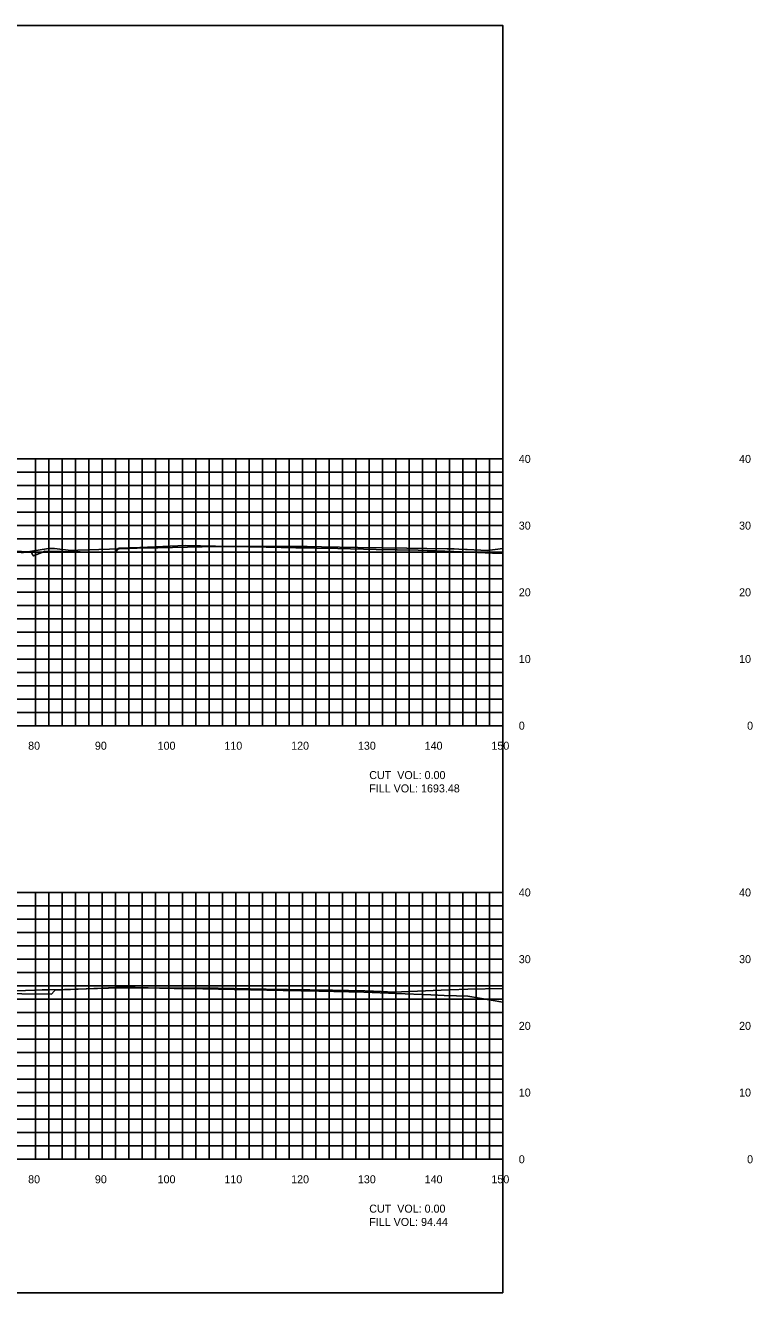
# Model space of a CAD drawing. Extents: x 1797518 to 1804843, y 248068 to 251132.
# Drawn here: x 1802709.5 to 1802818.4, y 250079.4 to 250269.4 of the extents above; entities that cross this region are included whole.
import ezdxf

# ---------------------------------------------------------------- set-up
doc = ezdxf.new("R2010")
doc.units = 0
for name, color, linetype in [('10', 7, 'Continuous'), ('31', 7, 'Continuous'), ('60', 7, 'Continuous'), ('ANNO-TXT', 7, 'Continuous'), ('CL-CNST', 7, 'Continuous'), ('Level 62', 7, 'Continuous'), ('M-ROADS', 7, 'Continuous')]:
    doc.layers.add(name, color=color, linetype=linetype)

msp = doc.modelspace()

# ---------------------------------------------------------------- linework, layer by layer
msp.add_lwpolyline([(1802481, 250079.43), (1802781, 250079.43), (1802781, 250269.43), (1802481, 250269.43)], close=True)
at = {"layer": '60'}
for p, q in [((1802781, 250164.43), (1802781, 250204.43)), ((1802781.06, 250204.43), (1802781, 250204.43)), ((1802781.06, 250194.43), (1802781, 250194.43)), ((1802781.06, 250184.43), (1802781, 250184.43)), ((1802781.06, 250174.43), (1802781, 250174.43)), ((1802481, 250164.43), (1802781, 250164.43)), ((1802711, 250164.37), (1802711, 250164.43)), ((1802721, 250164.37), (1802721, 250164.43)), ((1802731, 250164.37), (1802731, 250164.43)), ((1802741, 250164.37), (1802741, 250164.43)), ((1802751, 250164.37), (1802751, 250164.43)), ((1802761, 250164.37), (1802761, 250164.43)), ((1802771, 250164.37), (1802771, 250164.43)), ((1802781, 250164.37), (1802781, 250164.43)), ((1802781.06, 250164.43), (1802781, 250164.43)), ((1802781, 250099.43), (1802781, 250139.43)), ((1802781.06, 250139.43), (1802781, 250139.43)), ((1802781.06, 250129.43), (1802781, 250129.43)), ((1802781.06, 250119.43), (1802781, 250119.43)), ((1802781.06, 250109.43), (1802781, 250109.43)), ((1802481, 250099.43), (1802781, 250099.43)), ((1802711, 250099.37), (1802711, 250099.43)), ((1802721, 250099.37), (1802721, 250099.43)), ((1802731, 250099.37), (1802731, 250099.43)), ((1802741, 250099.37), (1802741, 250099.43)), ((1802751, 250099.37), (1802751, 250099.43)), ((1802761, 250099.37), (1802761, 250099.43)), ((1802771, 250099.37), (1802771, 250099.43)), ((1802781, 250099.37), (1802781, 250099.43)), ((1802781.06, 250099.43), (1802781, 250099.43))]:
    msp.add_line(p, q, dxfattribs=at)
at = {"layer": 'CL-CNST'}
for points in [[(1802707.78, 250190.58), (1802710.13, 250190.49), (1802710.29, 250190.48), (1802710.35, 250190.48), (1802710.59, 250190.02), (1802710.68, 250189.88), (1802711.96, 250190.4), (1802712.4, 250190.58), (1802715.12, 250190.53), (1802722.9, 250190.42), (1802723.07, 250190.61), (1802723.45, 250191.03), (1802726.65, 250191.17), (1802733.49, 250191.45), (1802737.96, 250191.36), (1802745.55, 250191.2), (1802750.02, 250191.11), (1802756.27, 250190.98), (1802762.05, 250190.86), (1802768.31, 250190.74), (1802773.66, 250190.53), (1802778.34, 250190.35), (1802779.46, 250190.31), (1802780.35, 250190.28), (1802781, 250190.25)], [(1802704.47, 250124.27), (1802713.39, 250124.19), (1802713.78, 250124.63), (1802713.94, 250124.8), (1802720.89, 250125.09), (1802723.99, 250125.21), (1802731.8, 250125.05), (1802736.05, 250124.96), (1802740.75, 250124.87), (1802748.11, 250124.72), (1802753.45, 250124.61), (1802760.18, 250124.47), (1802765.1, 250124.28), (1802770.23, 250124.08), (1802771.27, 250124.04), (1802772.24, 250124), (1802774.09, 250123.93), (1802775.76, 250123.87), (1802781, 250123)]]:
    msp.add_lwpolyline(points, dxfattribs=at)
at = {"layer": 'Level 62'}
for p, q in [((1802481, 250204.43), (1802781, 250204.43)), ((1802711, 250164.43), (1802711, 250204.43)), ((1802713, 250164.43), (1802713, 250204.43)), ((1802715, 250164.43), (1802715, 250204.43)), ((1802717, 250164.43), (1802717, 250204.43)), ((1802719, 250164.43), (1802719, 250204.43)), ((1802721, 250164.43), (1802721, 250204.43)), ((1802723, 250164.43), (1802723, 250204.43)), ((1802725, 250164.43), (1802725, 250204.43)), ((1802727, 250164.43), (1802727, 250204.43)), ((1802729, 250164.43), (1802729, 250204.43)), ((1802731, 250164.43), (1802731, 250204.43)), ((1802733, 250164.43), (1802733, 250204.43)), ((1802735, 250164.43), (1802735, 250204.43)), ((1802737, 250164.43), (1802737, 250204.43)), ((1802739, 250164.43), (1802739, 250204.43)), ((1802741, 250164.43), (1802741, 250204.43)), ((1802743, 250164.43), (1802743, 250204.43)), ((1802745, 250164.43), (1802745, 250204.43)), ((1802747, 250164.43), (1802747, 250204.43)), ((1802749, 250164.43), (1802749, 250204.43)), ((1802751, 250164.43), (1802751, 250204.43)), ((1802753, 250164.43), (1802753, 250204.43)), ((1802755, 250164.43), (1802755, 250204.43)), ((1802757, 250164.43), (1802757, 250204.43)), ((1802759, 250164.43), (1802759, 250204.43)), ((1802761, 250164.43), (1802761, 250204.43)), ((1802763, 250164.43), (1802763, 250204.43)), ((1802765, 250164.43), (1802765, 250204.43)), ((1802767, 250164.43), (1802767, 250204.43)), ((1802769, 250164.43), (1802769, 250204.43)), ((1802771, 250164.43), (1802771, 250204.43)), ((1802773, 250164.43), (1802773, 250204.43)), ((1802775, 250164.43), (1802775, 250204.43)), ((1802777, 250164.43), (1802777, 250204.43)), ((1802779, 250164.43), (1802779, 250204.43)), ((1802781, 250164.43), (1802781, 250204.43)), ((1802481, 250202.43), (1802781, 250202.43)), ((1802481, 250200.43), (1802781, 250200.43)), ((1802481, 250198.43), (1802781, 250198.43)), ((1802481, 250196.43), (1802781, 250196.43)), ((1802481, 250194.43), (1802781, 250194.43)), ((1802481, 250192.43), (1802781, 250192.43)), ((1802481, 250190.43), (1802781, 250190.43)), ((1802481, 250188.43), (1802781, 250188.43)), ((1802481, 250186.43), (1802781, 250186.43)), ((1802481, 250184.43), (1802781, 250184.43)), ((1802481, 250182.43), (1802781, 250182.43)), ((1802481, 250180.43), (1802781, 250180.43)), ((1802481, 250178.43), (1802781, 250178.43)), ((1802481, 250176.43), (1802781, 250176.43)), ((1802481, 250174.43), (1802781, 250174.43)), ((1802481, 250172.43), (1802781, 250172.43)), ((1802481, 250170.43), (1802781, 250170.43)), ((1802481, 250168.43), (1802781, 250168.43)), ((1802481, 250166.43), (1802781, 250166.43)), ((1802481, 250164.43), (1802781, 250164.43)), ((1802481, 250139.43), (1802781, 250139.43)), ((1802711, 250099.43), (1802711, 250139.43)), ((1802713, 250099.43), (1802713, 250139.43)), ((1802715, 250099.43), (1802715, 250139.43)), ((1802717, 250099.43), (1802717, 250139.43)), ((1802719, 250099.43), (1802719, 250139.43)), ((1802721, 250099.43), (1802721, 250139.43)), ((1802723, 250099.43), (1802723, 250139.43)), ((1802725, 250099.43), (1802725, 250139.43)), ((1802727, 250099.43), (1802727, 250139.43)), ((1802729, 250099.43), (1802729, 250139.43)), ((1802731, 250099.43), (1802731, 250139.43)), ((1802733, 250099.43), (1802733, 250139.43)), ((1802735, 250099.43), (1802735, 250139.43)), ((1802737, 250099.43), (1802737, 250139.43)), ((1802739, 250099.43), (1802739, 250139.43)), ((1802741, 250099.43), (1802741, 250139.43)), ((1802743, 250099.43), (1802743, 250139.43)), ((1802745, 250099.43), (1802745, 250139.43)), ((1802747, 250099.43), (1802747, 250139.43)), ((1802749, 250099.43), (1802749, 250139.43)), ((1802751, 250099.43), (1802751, 250139.43)), ((1802753, 250099.43), (1802753, 250139.43)), ((1802755, 250099.43), (1802755, 250139.43)), ((1802757, 250099.43), (1802757, 250139.43)), ((1802759, 250099.43), (1802759, 250139.43)), ((1802761, 250099.43), (1802761, 250139.43)), ((1802763, 250099.43), (1802763, 250139.43)), ((1802765, 250099.43), (1802765, 250139.43)), ((1802767, 250099.43), (1802767, 250139.43)), ((1802769, 250099.43), (1802769, 250139.43)), ((1802771, 250099.43), (1802771, 250139.43)), ((1802773, 250099.43), (1802773, 250139.43)), ((1802775, 250099.43), (1802775, 250139.43)), ((1802777, 250099.43), (1802777, 250139.43)), ((1802779, 250099.43), (1802779, 250139.43)), ((1802781, 250099.43), (1802781, 250139.43)), ((1802481, 250137.43), (1802781, 250137.43)), ((1802481, 250135.43), (1802781, 250135.43)), ((1802481, 250133.43), (1802781, 250133.43)), ((1802481, 250131.43), (1802781, 250131.43)), ((1802481, 250129.43), (1802781, 250129.43)), ((1802481, 250127.43), (1802781, 250127.43)), ((1802481, 250125.43), (1802781, 250125.43)), ((1802481, 250123.43), (1802781, 250123.43)), ((1802481, 250121.43), (1802781, 250121.43)), ((1802481, 250119.43), (1802781, 250119.43)), ((1802481, 250117.43), (1802781, 250117.43)), ((1802481, 250115.43), (1802781, 250115.43)), ((1802481, 250113.43), (1802781, 250113.43)), ((1802481, 250111.43), (1802781, 250111.43)), ((1802481, 250109.43), (1802781, 250109.43)), ((1802481, 250107.43), (1802781, 250107.43)), ((1802481, 250105.43), (1802781, 250105.43)), ((1802481, 250103.43), (1802781, 250103.43)), ((1802481, 250101.43), (1802781, 250101.43)), ((1802481, 250099.43), (1802781, 250099.43))]:
    msp.add_line(p, q, dxfattribs=at)
at = {"layer": 'M-ROADS'}
for points in [[(1802708.9, 250190.36), (1802712.93, 250190.98), (1802713.84, 250190.98), (1802715.89, 250190.74), (1802716.22, 250190.7), (1802716.65, 250190.72), (1802717.35, 250190.74), (1802722.09, 250190.91), (1802724.99, 250191), (1802725.72, 250191.03), (1802726.24, 250191.04), (1802729.34, 250191.1), (1802735.99, 250191.25), (1802737.52, 250191.29), (1802738.24, 250191.31), (1802744.6, 250191.31), (1802750.26, 250191.3), (1802751.7, 250191.28), (1802753.86, 250191.24), (1802759.31, 250191.17), (1802762.9, 250191.11), (1802766.61, 250191.05), (1802772.67, 250190.94), (1802773.74, 250190.93), (1802774.4, 250190.91), (1802775.44, 250190.87), (1802775.65, 250190.85), (1802777.71, 250190.75), (1802778.71, 250190.71), (1802781, 250191.01)], [(1802706.81, 250124.64), (1802710.86, 250124.79), (1802712, 250124.81), (1802712.12, 250124.81), (1802712.93, 250124.83), (1802715.36, 250124.9), (1802721.95, 250125.07), (1802724.13, 250125.12), (1802729.59, 250125.09), (1802736.19, 250125.1), (1802736.88, 250125.09), (1802738.38, 250125.07), (1802745.54, 250124.95), (1802748.77, 250124.89), (1802755.5, 250124.77), (1802760.36, 250124.69), (1802760.98, 250124.65), (1802761.62, 250124.62), (1802762.77, 250124.57), (1802764.67, 250124.48), (1802765.85, 250124.52), (1802768.24, 250124.64), (1802771.79, 250124.79), (1802773.1, 250124.85), (1802775.76, 250124.94), (1802781, 250125.02)]]:
    msp.add_lwpolyline(points, dxfattribs=at)

# ---------------------------------------------------------------- texts
at = {"layer": '10'}
for s, p in [('80', (1802709.9, 250160.83)), ('90', (1802719.9, 250160.83)), ('100', (1802729.3, 250160.83)), ('110', (1802739.3, 250160.83)), ('120', (1802749.3, 250160.83)), ('130', (1802759.3, 250160.83)), ('140', (1802769.3, 250160.83)), ('150', (1802779.3, 250160.83)), ('80', (1802709.9, 250095.83)), ('90', (1802719.9, 250095.83)), ('100', (1802729.3, 250095.83)), ('110', (1802739.3, 250095.83)), ('120', (1802749.3, 250095.83)), ('130', (1802759.3, 250095.83)), ('140', (1802769.3, 250095.83)), ('150', (1802779.3, 250095.83))]:
    msp.add_text(s, height=1.2, dxfattribs=at).set_placement(p)
at = {"layer": '31'}
for s, p in [('40', (1802783.4, 250203.83)), ('40', (1802816.4, 250203.83)), ('30', (1802783.4, 250193.83)), ('30', (1802816.4, 250193.83)), ('20', (1802783.4, 250183.83)), ('20', (1802816.4, 250183.83)), ('10', (1802783.4, 250173.83)), ('10', (1802816.4, 250173.83)), ('0', (1802783.4, 250163.83)), ('0', (1802817.6, 250163.83)), ('40', (1802783.4, 250138.83)), ('40', (1802816.4, 250138.83)), ('30', (1802783.4, 250128.83)), ('30', (1802816.4, 250128.83)), ('20', (1802783.4, 250118.83)), ('20', (1802816.4, 250118.83)), ('10', (1802783.4, 250108.83)), ('10', (1802816.4, 250108.83)), ('0', (1802783.4, 250098.83)), ('0', (1802817.6, 250098.83))]:
    msp.add_text(s, height=1.2, dxfattribs=at).set_placement(p)
at = {"layer": 'ANNO-TXT'}
for s, p in [('CUT  VOL: 0.00', (1802761, 250156.43)), ('FILL VOL: 1693.48', (1802761, 250154.43)), ('CUT  VOL: 0.00', (1802761, 250091.43)), ('FILL VOL: 94.44', (1802761, 250089.43))]:
    msp.add_text(s, height=1.2, dxfattribs=at).set_placement(p)

doc.saveas('drawing.dxf')
